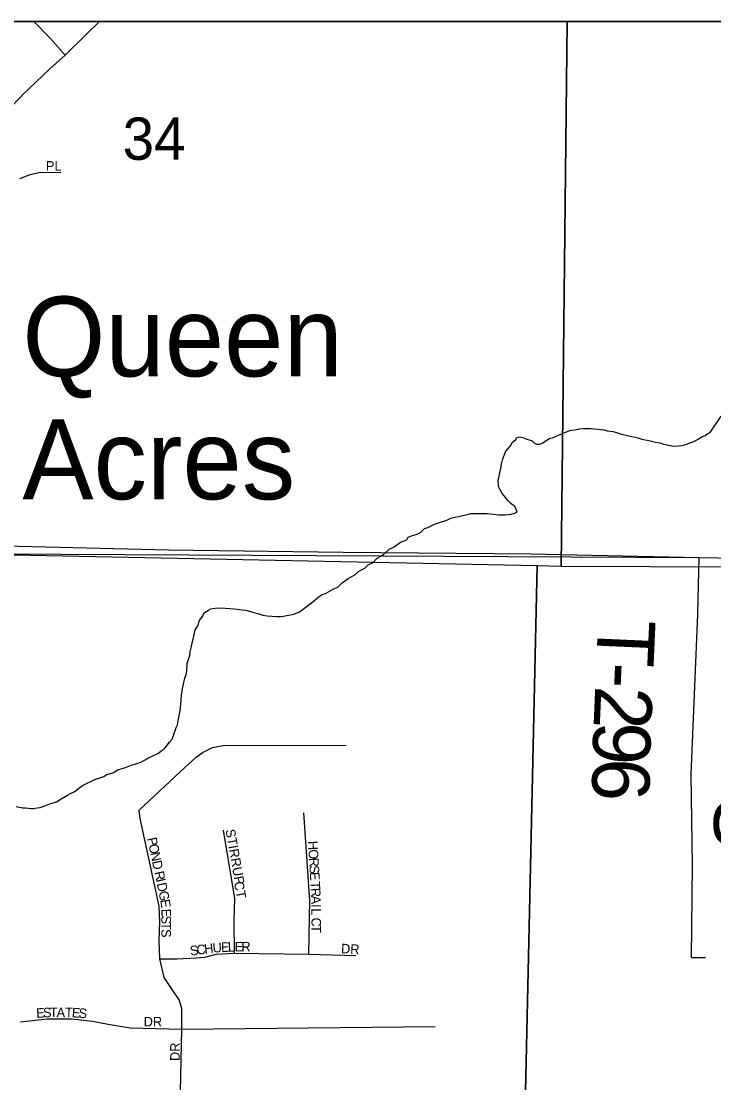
# Model space of a CAD drawing. Extents: x 0 to 34, y -2.3 to 22.
# Drawn here: x 6.13 to 6.815, y 19.85 to 20.9 of the extents above; entities that cross this region are included whole.
import ezdxf

# ---------------------------------------------------------------- set-up
doc = ezdxf.new("R2010")
doc.units = 0
for name, color, linetype in [('GM_X_County', 7, 'Continuous'), ('GM_X_County_Road', 7, 'Continuous'), ('GM_X_Minor_River', 7, 'Continuous'), ('GM_X_Section', 7, 'Continuous'), ('GM_X_Section_Text', 7, 'Continuous'), ('GM_X_State_Route', 7, 'Continuous'), ('GM_X_Township', 7, 'Continuous'), ('GM_X_Township_Road', 7, 'Continuous'), ('GM_X_Township_Road_Text', 7, 'Continuous'), ('GM_X_Township_Subdivision', 7, 'Continuous'), ('GM_X_Township_Subdivision_Text', 7, 'Continuous'), ('GM_X_Unincorporated_Text', 7, 'Continuous'), ('SH_Data', 7, 'Continuous')]:
    doc.layers.add(name, color=color, linetype=linetype)

msp = doc.modelspace()

# ---------------------------------------------------------------- linework, layer by layer
at = {"layer": 'GM_X_County'}
msp.add_line((8.8792, 20.8994), (2.0792, 20.8994), dxfattribs=at)
at = {"layer": 'GM_X_County_Road'}
for p, q in [((6.1141, 20.3811), (6.2758, 20.377)), ((6.2758, 20.377), (6.4487, 20.3747)), ((6.4487, 20.3747), (6.6349, 20.3731)), ((6.6349, 20.3731), (6.8005, 20.3694)), ((6.8005, 20.3694), (6.9133, 20.3674))]:
    msp.add_line(p, q, dxfattribs=at)
at = {"layer": 'GM_X_Minor_River'}
for p, q in [((6.812, 20.4931), (6.8226, 20.5094)), ((6.6617, 20.4904), (6.664, 20.4915)), ((6.664, 20.4915), (6.669, 20.4933)), ((6.669, 20.4933), (6.6729, 20.4951)), ((6.6729, 20.4951), (6.6751, 20.4954)), ((6.6751, 20.4954), (6.6778, 20.4957)), ((6.6778, 20.4957), (6.6828, 20.4967)), ((6.6828, 20.4967), (6.6866, 20.497)), ((6.6866, 20.497), (6.6942, 20.4972)), ((6.6942, 20.4972), (6.6969, 20.4967)), ((6.6969, 20.4967), (6.7006, 20.4963)), ((6.7006, 20.4963), (6.7067, 20.4957)), ((6.7067, 20.4957), (6.7101, 20.4949)), ((6.7101, 20.4949), (6.7132, 20.4944)), ((6.7132, 20.4944), (6.7158, 20.494)), ((6.7158, 20.494), (6.7203, 20.4927)), ((6.7203, 20.4927), (6.723, 20.4919)), ((6.723, 20.4919), (6.7313, 20.4898)), ((6.807, 20.4902), (6.8097, 20.492)), ((6.8097, 20.492), (6.812, 20.4931)), ((6.6143, 20.4798), (6.6163, 20.4836)), ((6.6163, 20.4836), (6.6194, 20.4858)), ((6.6194, 20.4858), (6.6206, 20.488)), ((6.6206, 20.488), (6.6233, 20.4887)), ((6.6233, 20.4887), (6.6256, 20.4886)), ((6.6256, 20.4886), (6.6305, 20.4866)), ((6.6305, 20.4866), (6.6327, 20.4858)), ((6.6327, 20.4858), (6.6357, 20.485)), ((6.6357, 20.485), (6.638, 20.4826)), ((6.638, 20.4826), (6.6402, 20.4814)), ((6.6402, 20.4814), (6.6433, 20.4817)), ((6.6433, 20.4817), (6.6456, 20.4825)), ((6.6456, 20.4825), (6.6502, 20.4854)), ((6.6502, 20.4854), (6.6529, 20.4872)), ((6.6529, 20.4872), (6.656, 20.4879)), ((6.656, 20.4879), (6.6617, 20.4904)), ((6.7313, 20.4898), (6.7374, 20.4885)), ((6.7374, 20.4885), (6.7404, 20.4877)), ((6.7404, 20.4877), (6.7442, 20.4865)), ((6.7442, 20.4865), (6.751, 20.4851)), ((6.751, 20.4851), (6.7578, 20.4835)), ((6.7578, 20.4835), (6.7623, 20.483)), ((6.7623, 20.483), (6.7657, 20.4817)), ((6.7657, 20.4817), (6.768, 20.4813)), ((6.768, 20.4813), (6.7706, 20.4805)), ((6.7843, 20.4801), (6.7889, 20.4815)), ((6.7889, 20.4815), (6.7916, 20.483)), ((6.7916, 20.483), (6.795, 20.4837)), ((6.795, 20.4837), (6.7977, 20.4851)), ((6.7977, 20.4851), (6.8001, 20.4866)), ((6.8001, 20.4866), (6.8032, 20.4888)), ((6.8032, 20.4888), (6.807, 20.4902)), ((6.6064, 20.466), (6.6084, 20.4712)), ((6.6084, 20.4712), (6.6096, 20.4746)), ((6.6096, 20.4746), (6.6143, 20.4798)), ((6.7706, 20.4805), (6.774, 20.48)), ((6.774, 20.48), (6.7763, 20.4796)), ((6.7763, 20.4796), (6.7801, 20.4799)), ((6.7801, 20.4799), (6.7843, 20.4801)), ((6.6043, 20.4557), (6.6056, 20.4633)), ((6.6056, 20.4633), (6.6064, 20.466)), ((6.6026, 20.4482), (6.6038, 20.4535)), ((6.6038, 20.4535), (6.6043, 20.4557)), ((6.6021, 20.4459), (6.6026, 20.4482)), ((6.6024, 20.4398), (6.6021, 20.4459)), ((6.6038, 20.4371), (6.6024, 20.4398)), ((6.6064, 20.4325), (6.6038, 20.4371)), ((6.6093, 20.4287), (6.6064, 20.4325)), ((6.6119, 20.4255), (6.6093, 20.4287)), ((6.6149, 20.4224), (6.6119, 20.4255)), ((6.6183, 20.4201), (6.6149, 20.4224)), ((6.6197, 20.4178), (6.6183, 20.4201)), ((6.6208, 20.4143), (6.6197, 20.4178)), ((6.5514, 20.4065), (6.5552, 20.4083)), ((6.5552, 20.4083), (6.5579, 20.409)), ((6.5579, 20.409), (6.564, 20.4104)), ((6.564, 20.4104), (6.5713, 20.4121)), ((6.5713, 20.4121), (6.5751, 20.4128)), ((6.5751, 20.4128), (6.5804, 20.413)), ((6.5804, 20.413), (6.5911, 20.4128)), ((6.5911, 20.4128), (6.5945, 20.4127)), ((6.5945, 20.4127), (6.5975, 20.4122)), ((6.5975, 20.4122), (6.6029, 20.4117)), ((6.6029, 20.4117), (6.6089, 20.4116)), ((6.6089, 20.4116), (6.6124, 20.4119)), ((6.6124, 20.4119), (6.615, 20.4122)), ((6.615, 20.4122), (6.6181, 20.4132)), ((6.6181, 20.4132), (6.6208, 20.4143)), ((6.5252, 20.3943), (6.5291, 20.398)), ((6.5291, 20.398), (6.5326, 20.399)), ((6.5326, 20.399), (6.5391, 20.4023)), ((6.5391, 20.4023), (6.5449, 20.4044)), ((6.5449, 20.4044), (6.5514, 20.4065)), ((6.5056, 20.3845), (6.5118, 20.387)), ((6.5118, 20.387), (6.513, 20.3896)), ((6.513, 20.3896), (6.5172, 20.3911)), ((6.5172, 20.3911), (6.5218, 20.3925)), ((6.5218, 20.3925), (6.5252, 20.3943)), ((6.4886, 20.3724), (6.4941, 20.3776)), ((6.4941, 20.3776), (6.4991, 20.3801)), ((6.4991, 20.3801), (6.5056, 20.3845)), ((6.4782, 20.3643), (6.4824, 20.3688)), ((6.4824, 20.3688), (6.4859, 20.3706)), ((6.4859, 20.3706), (6.4886, 20.3724)), ((6.4604, 20.3522), (6.4639, 20.3555)), ((6.4639, 20.3555), (6.4662, 20.357)), ((6.4662, 20.357), (6.47, 20.3588)), ((6.47, 20.3588), (6.4739, 20.3625)), ((6.4739, 20.3625), (6.4782, 20.3643)), ((6.4438, 20.3405), (6.4476, 20.3442)), ((6.4476, 20.3442), (6.4535, 20.3486)), ((6.4535, 20.3486), (6.4565, 20.3504)), ((6.4565, 20.3504), (6.4604, 20.3522)), ((6.4272, 20.3325), (6.4314, 20.3339)), ((6.4314, 20.3339), (6.438, 20.3379)), ((6.438, 20.3379), (6.4438, 20.3405)), ((6.4121, 20.3207), (6.4187, 20.3255)), ((6.4187, 20.3255), (6.4237, 20.3299)), ((6.4237, 20.3299), (6.4272, 20.3325)), ((6.3092, 20.3108), (6.3116, 20.3149)), ((6.3116, 20.3149), (6.3154, 20.3174)), ((6.3154, 20.3174), (6.3177, 20.3185)), ((6.3177, 20.3185), (6.3239, 20.3195)), ((6.3239, 20.3195), (6.3318, 20.3193)), ((6.3318, 20.3193), (6.3413, 20.3187)), ((6.3413, 20.3187), (6.3485, 20.3178)), ((6.3485, 20.3178), (6.3523, 20.3173)), ((6.3523, 20.3173), (6.355, 20.3168)), ((6.355, 20.3168), (6.3591, 20.3152)), ((6.3591, 20.3152), (6.3618, 20.3148)), ((6.3618, 20.3148), (6.3644, 20.3139)), ((6.3644, 20.3139), (6.3693, 20.3123)), ((6.3898, 20.3114), (6.3998, 20.3134)), ((6.3998, 20.3134), (6.4055, 20.3156)), ((6.4055, 20.3156), (6.409, 20.3182)), ((6.409, 20.3182), (6.4121, 20.3207)), ((6.3048, 20.3018), (6.3065, 20.307)), ((6.3065, 20.307), (6.3092, 20.3108)), ((6.3693, 20.3123), (6.3735, 20.3118)), ((6.3735, 20.3118), (6.3826, 20.3112)), ((6.3826, 20.3112), (6.3868, 20.3111)), ((6.3868, 20.3111), (6.3898, 20.3114)), ((6.3003, 20.2886), (6.3024, 20.298)), ((6.3024, 20.298), (6.3048, 20.3018)), ((6.2982, 20.2799), (6.2995, 20.2863)), ((6.2995, 20.2863), (6.3003, 20.2886)), ((6.2944, 20.2644), (6.2969, 20.2723)), ((6.2969, 20.2723), (6.2974, 20.2761)), ((6.2974, 20.2761), (6.2982, 20.2799)), ((6.2939, 20.2568), (6.2944, 20.2644)), ((6.2905, 20.2429), (6.2922, 20.25)), ((6.2922, 20.25), (6.2934, 20.2538)), ((6.2934, 20.2538), (6.2939, 20.2568)), ((6.2888, 20.233), (6.2897, 20.2395)), ((6.2897, 20.2395), (6.2905, 20.2429)), ((6.2882, 20.2243), (6.2883, 20.2289)), ((6.2883, 20.2289), (6.2888, 20.233)), ((6.2873, 20.2179), (6.2877, 20.2209)), ((6.2877, 20.2209), (6.2882, 20.2243)), ((6.2847, 20.2039), (6.2859, 20.2099)), ((6.2859, 20.2099), (6.2873, 20.2179)), ((6.2814, 20.1952), (6.2835, 20.2012)), ((6.2835, 20.2012), (6.2847, 20.2039)), ((6.2735, 20.1825), (6.277, 20.1866)), ((6.277, 20.1866), (6.2794, 20.1896)), ((6.2794, 20.1896), (6.2814, 20.1952)), ((6.2661, 20.1758), (6.2685, 20.1781)), ((6.2685, 20.1781), (6.2716, 20.1799)), ((6.2716, 20.1799), (6.2735, 20.1825)), ((6.2435, 20.1654), (6.2484, 20.1668)), ((6.2484, 20.1668), (6.2534, 20.1697)), ((6.2534, 20.1697), (6.2558, 20.1712)), ((6.2558, 20.1712), (6.2584, 20.1722)), ((6.2584, 20.1722), (6.2661, 20.1758)), ((6.2147, 20.1547), (6.2208, 20.1565)), ((6.2208, 20.1565), (6.2258, 20.1594)), ((6.2258, 20.1594), (6.23, 20.1608)), ((6.23, 20.1608), (6.2335, 20.1615)), ((6.2335, 20.1615), (6.24, 20.1643)), ((6.24, 20.1643), (6.2435, 20.1654)), ((6.1916, 20.1443), (6.2024, 20.1493)), ((6.2024, 20.1493), (6.2051, 20.1504)), ((6.2051, 20.1504), (6.212, 20.1529)), ((6.212, 20.1529), (6.2147, 20.1547)), ((6.1696, 20.1308), (6.1758, 20.1344)), ((6.1758, 20.1344), (6.1781, 20.1355)), ((6.1781, 20.1355), (6.1831, 20.138)), ((6.1831, 20.138), (6.1885, 20.1421)), ((6.1885, 20.1421), (6.1916, 20.1443)), ((6.1489, 20.1222), (6.1535, 20.1236)), ((6.1535, 20.1236), (6.1585, 20.1257)), ((6.1585, 20.1257), (6.165, 20.1278)), ((6.165, 20.1278), (6.1696, 20.1308)), ((6.1253, 20.1231), (6.1318, 20.1218)), ((6.1318, 20.1218), (6.1344, 20.1218)), ((6.1344, 20.1218), (6.1375, 20.1213)), ((6.1375, 20.1213), (6.1398, 20.1212)), ((6.1398, 20.1212), (6.1424, 20.1212)), ((6.1424, 20.1212), (6.1459, 20.1219)), ((6.1459, 20.1219), (6.1489, 20.1222))]:
    msp.add_line(p, q, dxfattribs=at)
at = {"layer": 'GM_X_Section'}
for p, q in [((6.6703, 20.8994), (5.6728, 20.8994)), ((6.6643, 20.361), (6.6703, 20.8994)), ((6.6703, 20.8994), (6.6643, 20.361)), ((7.6777, 20.8994), (6.6703, 20.8994)), ((5.6658, 20.3811), (6.6408, 20.3616)), ((5.6658, 20.3811), (6.6408, 20.3616)), ((6.6408, 20.3616), (6.6178, 19.348)), ((6.6178, 19.348), (6.6408, 20.3616)), ((6.6408, 20.3616), (6.6643, 20.361)), ((6.6408, 20.3616), (6.6643, 20.361)), ((6.6643, 20.361), (7.6503, 20.3564)), ((6.6643, 20.361), (7.6503, 20.3564))]:
    msp.add_line(p, q, dxfattribs=at)
at = {"layer": 'GM_X_State_Route'}
for p, q in [((6.1943, 20.8869), (6.2074, 20.8994)), ((6.1735, 20.8664), (6.1943, 20.8869)), ((6.1586, 20.8529), (6.1735, 20.8664)), ((6.1309, 20.8265), (6.1586, 20.8529)), ((6.1172, 20.8124), (6.1307, 20.8263)), ((6.1307, 20.8263), (6.1309, 20.8265))]:
    msp.add_line(p, q, dxfattribs=at)
at = {"layer": 'GM_X_Township'}
for p, q in [((8.674, 20.8994), (2.6175, 20.8994)), ((6.0714, 20.3731), (6.8005, 20.3694)), ((6.0714, 20.3731), (6.8005, 20.3694)), ((6.8005, 20.3694), (6.9133, 20.3674)), ((6.8005, 20.3694), (6.9133, 20.3674))]:
    msp.add_line(p, q, dxfattribs=at)
at = {"layer": 'GM_X_Township_Road'}
for p, q in [((6.8005, 20.3694), (6.7996, 20.3283)), ((6.7996, 20.3283), (6.7993, 20.3135)), ((6.7993, 20.3135), (6.7928, 20.1547)), ((6.7928, 20.1547), (6.7941, 20.0646)), ((6.7941, 20.0646), (6.7931, 19.9735)), ((6.7931, 19.9735), (6.8073, 19.9735))]:
    msp.add_line(p, q, dxfattribs=at)
at = {"layer": 'GM_X_Township_Subdivision'}
for p, q in [((6.1431, 20.8994), (6.1584, 20.8836)), ((6.1584, 20.8836), (6.1735, 20.8664)), ((6.1388, 20.748), (6.1286, 20.7442)), ((6.1494, 20.7502), (6.1388, 20.748)), ((6.1693, 20.7499), (6.1494, 20.7502)), ((6.3032, 20.172), (6.3103, 20.1767)), ((6.3103, 20.1767), (6.3195, 20.1815)), ((6.3195, 20.1815), (6.3301, 20.1835)), ((6.3301, 20.1835), (6.4518, 20.1837)), ((6.2919, 20.1616), (6.3032, 20.172)), ((6.2469, 20.1193), (6.2919, 20.1616)), ((6.2478, 20.1113), (6.2469, 20.1193)), ((6.4157, 20.0299), (6.4097, 20.1169)), ((6.2668, 20.0243), (6.2478, 20.1113)), ((6.3414, 20.032), (6.3304, 20.0995)), ((6.3408, 20.0107), (6.3414, 20.032)), ((6.4148, 19.9769), (6.4157, 20.0299)), ((6.2674, 20.0092), (6.2668, 20.0243)), ((6.2668, 19.9903), (6.2674, 20.0092)), ((6.3411, 19.9778), (6.3408, 20.0107)), ((6.2674, 19.9725), (6.2668, 19.9903)), ((6.3118, 19.974), (6.323, 19.9769)), ((6.323, 19.9769), (6.3411, 19.9778)), ((6.3411, 19.9778), (6.4148, 19.9769)), ((6.4148, 19.9769), (6.4612, 19.9757)), ((6.2715, 19.9538), (6.2674, 19.9725)), ((6.2674, 19.9725), (6.2842, 19.9725)), ((6.2842, 19.9725), (6.3032, 19.9734)), ((6.3032, 19.9734), (6.3118, 19.974)), ((6.2801, 19.9411), (6.2715, 19.9538)), ((6.2863, 19.9319), (6.2801, 19.9411)), ((6.289, 19.9231), (6.2863, 19.9319)), ((6.2891, 19.9028), (6.289, 19.9231)), ((6.1293, 19.9099), (6.1559, 19.9131)), ((6.1559, 19.9131), (6.1802, 19.9129)), ((6.1802, 19.9129), (6.2006, 19.9108)), ((6.2006, 19.9108), (6.2163, 19.9078)), ((6.2163, 19.9078), (6.2379, 19.904)), ((6.2379, 19.904), (6.2891, 19.9028)), ((6.2891, 19.9028), (6.5397, 19.9054)), ((6.2837, 19.6447), (6.2891, 19.9028))]:
    msp.add_line(p, q, dxfattribs=at)
at = {"layer": 'SH_Data'}
msp.add_line((2.1, 20.9), (8.9, 20.9), dxfattribs=at)

# ---------------------------------------------------------------- texts
at = {"layer": 'GM_X_Section_Text'}
msp.add_text('34', height=0.04186, rotation=0, dxfattribs=at).set_placement((6.2305, 20.7629))
at = {"layer": 'GM_X_Township_Road_Text'}
for s, rotation, p in [('T', 267.4578, (6.7011, 20.3089)), ('-', 267.4825, (6.6992, 20.2664)), ('2', 267.5748, (6.6982, 20.243)), ('9', 267.9446, (6.6967, 20.2076)), ('6', 269.4312, (6.6954, 20.171)), ('S', 270.0325, (6.8156, 20.1318))]:
    msp.add_text(s, height=0.0568, rotation=rotation, dxfattribs=at).set_placement(p)
at = {"layer": 'GM_X_Township_Subdivision_Text'}
for s, rotation, p in [('PL', 0, (6.1546, 20.7521)), ('P', 281.9516, (6.2547, 20.0915)), ('STIRRUP', 280.1249, (6.3322, 20.0998)), ('O', 281.9569, (6.2561, 20.085)), ('H', 273.2587, (6.4139, 20.0888)), ('N', 281.9569, (6.2578, 20.0769)), ('O', 273.2532, (6.4144, 20.0804)), ('R', 273.2564, (6.4149, 20.0721)), ('D', 281.9569, (6.2595, 20.0687)), ('S', 273.2608, (6.4153, 20.0646)), ('R', 281.9574, (6.2618, 20.0581)), ('I', 281.9528, (6.2633, 20.0508)), ('E', 273.2526, (6.4157, 20.058)), ('D', 281.9569, (6.2642, 20.0467)), ('CT', 280.0098, (6.3406, 20.0481)), ('T', 273.2526, (6.4162, 20.0488)), ('R', 273.2594, (6.4166, 20.0422)), ('G', 281.9569, (6.2659, 20.0385)), ('E', 279.1637, (6.2676, 20.0305)), ('A', 271.7271, (6.417, 20.0348)), ('E', 270.5669, (6.2689, 20.0218)), ('I', 270.153, (6.4172, 20.0265)), ('L', 270.0068, (6.4173, 20.0223)), ('S', 270, (6.2689, 20.0152)), ('T', 269.9985, (6.2689, 20.0085)), ('C', 270.003, (6.4173, 20.0132)), ('S', 269.9985, (6.2689, 20.0018)), ('T', 270, (6.4173, 20.0057)), ('H', 7.4524, (6.3118, 19.9773)), ('U', 4.485, (6.3199, 19.9784)), ('E', 2.6646, (6.3281, 19.979)), ('L', 2.0496, (6.3348, 19.9793)), ('E', 0.5055, (6.3414, 19.9796)), ('R', 0.0243, (6.348, 19.9796)), ('DR', 356.8158, (6.4464, 19.9779)), ('S', 7.5486, (6.2977, 19.9754)), ('C', 7.5377, (6.3043, 19.9763)), ('S', 2.6237, (6.1519, 19.9143)), ('T', 0.3962, (6.1585, 19.9146)), ('A', 359.9016, (6.1651, 19.9146)), ('T', 359.235, (6.1734, 19.9146)), ('E', 356.4186, (6.18, 19.9145)), ('E', 4.252, (6.1453, 19.9138)), ('S', 355.4326, (6.1866, 19.9141)), ('DR', 0, (6.2513, 19.9054)), ('DR', 90, (6.287, 19.8712))]:
    msp.add_text(s, height=0.00947, rotation=rotation, dxfattribs=at).set_placement(p)
at = {"layer": 'GM_X_Unincorporated_Text'}
for s, p in [('Queen', (6.1313, 20.5486)), ('Acres', (6.1313, 20.427))]:
    msp.add_text(s, height=0.07898, rotation=0, dxfattribs=at).set_placement(p)

doc.saveas('drawing.dxf')
